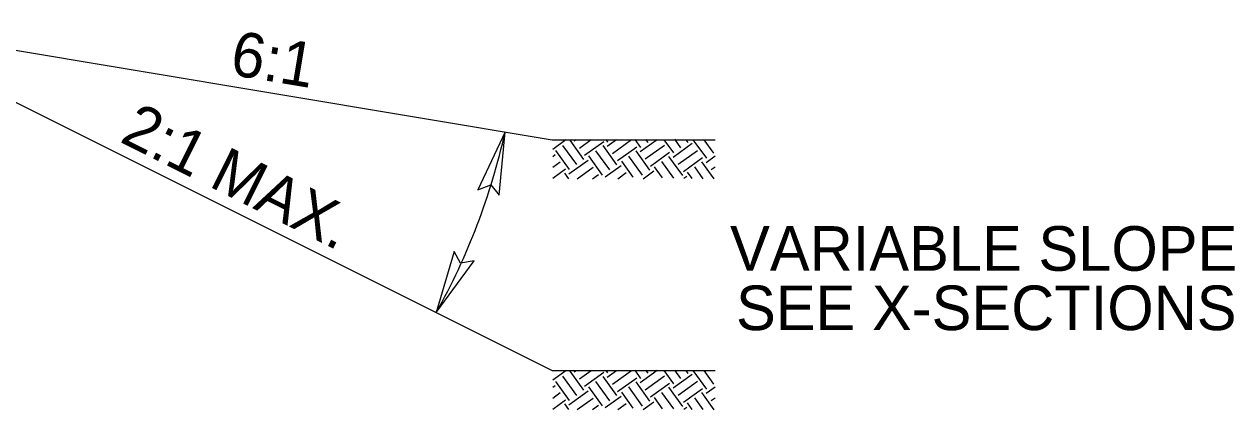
# Model space of a CAD drawing. Extents: x 1184121 to 1184397, y 1246506 to 1246661.
# Drawn here: x 1184249.47 to 1184276.61, y 1246565.28 to 1246573.92 of the extents above; entities that cross this region are included whole.
import ezdxf

# ---------------------------------------------------------------- set-up
doc = ezdxf.new("R2010")
doc.units = 0
doc.layers.add('Sheet Data Field CELL', color=7, linetype='Continuous')

msp = doc.modelspace()

# ---------------------------------------------------------------- linework, layer by layer
at = {"layer": 'Sheet Data Field CELL'}
for p, q in [((1184245.787, 1246573.92), (1184261.306, 1246571.333)), ((1184245.787, 1246573.92), (1184261.306, 1246566.16)), ((1184261.306, 1246571.333), (1184264.96, 1246571.333)), ((1184261.306, 1246571.333), (1184264.96, 1246571.333)), ((1184261.32, 1246571.122), (1184261.616, 1246571.334)), ((1184261.32, 1246571.122), (1184261.616, 1246571.334)), ((1184261.86, 1246570.776), (1184261.551, 1246571.206)), ((1184261.86, 1246570.776), (1184261.551, 1246571.206)), ((1184262.021, 1246570.892), (1184261.712, 1246571.322)), ((1184262.021, 1246570.892), (1184261.712, 1246571.322)), ((1184261.804, 1246571.307), (1184261.843, 1246571.335)), ((1184261.804, 1246571.307), (1184261.843, 1246571.335)), ((1184261.92, 1246571.146), (1184262.184, 1246571.336)), ((1184261.92, 1246571.146), (1184262.184, 1246571.336)), ((1184262.036, 1246570.985), (1184262.466, 1246571.293)), ((1184262.036, 1246570.985), (1184262.466, 1246571.293)), ((1184262.759, 1246570.771), (1184262.45, 1246571.201)), ((1184262.759, 1246570.771), (1184262.45, 1246571.201)), ((1184262.558, 1246571.278), (1184262.516, 1246571.337)), ((1184262.558, 1246571.278), (1184262.516, 1246571.337)), ((1184262.543, 1246571.186), (1184262.753, 1246571.337)), ((1184262.543, 1246571.186), (1184262.753, 1246571.337)), ((1184262.659, 1246571.025), (1184263.088, 1246571.334)), ((1184262.659, 1246571.025), (1184263.088, 1246571.334)), ((1184262.774, 1246570.864), (1184263.204, 1246571.172)), ((1184262.774, 1246570.864), (1184263.204, 1246571.172)), ((1184263.296, 1246571.157), (1184263.166, 1246571.338)), ((1184263.296, 1246571.157), (1184263.166, 1246571.338)), ((1184263.281, 1246571.065), (1184263.664, 1246571.34)), ((1184263.281, 1246571.065), (1184263.664, 1246571.34)), ((1184263.397, 1246570.904), (1184263.827, 1246571.213)), ((1184263.397, 1246570.904), (1184263.827, 1246571.213)), ((1184263.457, 1246571.273), (1184263.41, 1246571.339)), ((1184263.457, 1246571.273), (1184263.41, 1246571.339)), ((1184264.035, 1246571.036), (1184263.821, 1246571.333)), ((1184264.035, 1246571.036), (1184263.821, 1246571.333)), ((1184264.02, 1246570.944), (1184264.449, 1246571.253)), ((1184264.02, 1246570.944), (1184264.449, 1246571.253)), ((1184264.196, 1246571.152), (1184264.06, 1246571.341)), ((1184264.196, 1246571.152), (1184264.06, 1246571.341)), ((1184264.357, 1246571.268), (1184264.31, 1246571.333)), ((1184264.357, 1246571.268), (1184264.31, 1246571.333)), ((1184264.773, 1246570.915), (1184264.473, 1246571.333)), ((1184264.773, 1246570.915), (1184264.473, 1246571.333)), ((1184264.934, 1246571.031), (1184264.717, 1246571.333)), ((1184264.934, 1246571.031), (1184264.717, 1246571.333)), ((1184261.32, 1246570.959), (1184261.375, 1246570.998)), ((1184261.32, 1246570.959), (1184261.375, 1246570.998)), ((1184261.699, 1246570.661), (1184261.39, 1246571.09)), ((1184261.699, 1246570.661), (1184261.39, 1246571.09)), ((1184261.683, 1246570.568), (1184262.113, 1246570.877)), ((1184261.683, 1246570.568), (1184262.113, 1246570.877)), ((1184262.437, 1246570.54), (1184262.128, 1246570.969)), ((1184262.437, 1246570.54), (1184262.128, 1246570.969)), ((1184262.598, 1246570.656), (1184262.289, 1246571.085)), ((1184262.598, 1246570.656), (1184262.289, 1246571.085)), ((1184263.124, 1246570.49), (1184262.867, 1246570.849)), ((1184263.124, 1246570.49), (1184262.867, 1246570.849)), ((1184263.337, 1246570.535), (1184263.028, 1246570.964)), ((1184263.337, 1246570.535), (1184263.028, 1246570.964)), ((1184263.498, 1246570.65), (1184263.189, 1246571.08)), ((1184263.498, 1246570.65), (1184263.189, 1246571.08)), ((1184263.513, 1246570.743), (1184263.942, 1246571.051)), ((1184263.513, 1246570.743), (1184263.942, 1246571.051)), ((1184264.033, 1246570.472), (1184263.766, 1246570.843)), ((1184264.033, 1246570.472), (1184263.766, 1246570.843)), ((1184264.236, 1246570.53), (1184263.927, 1246570.959)), ((1184264.236, 1246570.53), (1184263.927, 1246570.959)), ((1184264.135, 1246570.783), (1184264.565, 1246571.092)), ((1184264.135, 1246570.783), (1184264.565, 1246571.092)), ((1184264.251, 1246570.622), (1184264.681, 1246570.931)), ((1184264.251, 1246570.622), (1184264.681, 1246570.931)), ((1184264.758, 1246570.823), (1184264.96, 1246570.968)), ((1184264.758, 1246570.823), (1184264.96, 1246570.968)), ((1184261.32, 1246570.714), (1184261.49, 1246570.837)), ((1184261.32, 1246570.714), (1184261.49, 1246570.837)), ((1184261.32, 1246570.47), (1184261.606, 1246570.676)), ((1184261.32, 1246570.47), (1184261.606, 1246570.676)), ((1184261.681, 1246570.459), (1184261.591, 1246570.583)), ((1184261.681, 1246570.459), (1184261.591, 1246570.583)), ((1184261.871, 1246570.459), (1184262.229, 1246570.716)), ((1184261.871, 1246570.459), (1184262.229, 1246570.716)), ((1184262.499, 1246570.503), (1184262.852, 1246570.756)), ((1184262.499, 1246570.503), (1184262.852, 1246570.756)), ((1184262.778, 1246570.459), (1184262.967, 1246570.595)), ((1184262.778, 1246570.459), (1184262.967, 1246570.595)), ((1184263.345, 1246570.459), (1184263.59, 1246570.635)), ((1184263.345, 1246570.459), (1184263.59, 1246570.635)), ((1184263.785, 1246570.477), (1184263.605, 1246570.728)), ((1184263.785, 1246570.477), (1184263.605, 1246570.728)), ((1184264.446, 1246570.464), (1184264.343, 1246570.607)), ((1184264.446, 1246570.464), (1184264.343, 1246570.607)), ((1184264.694, 1246570.459), (1184264.505, 1246570.723)), ((1184264.694, 1246570.459), (1184264.505, 1246570.723)), ((1184264.942, 1246570.454), (1184264.666, 1246570.838)), ((1184264.942, 1246570.454), (1184264.666, 1246570.838)), ((1184264.874, 1246570.662), (1184264.96, 1246570.724)), ((1184264.874, 1246570.662), (1184264.96, 1246570.724)), ((1184262.211, 1246570.459), (1184262.345, 1246570.555)), ((1184262.211, 1246570.459), (1184262.345, 1246570.555)), ((1184264.263, 1246570.467), (1184264.328, 1246570.514)), ((1184264.263, 1246570.467), (1184264.328, 1246570.514)), ((1184261.306, 1246566.16), (1184264.96, 1246566.16)), ((1184261.306, 1246566.16), (1184264.96, 1246566.16)), ((1184261.32, 1246565.948), (1184261.616, 1246566.161)), ((1184261.32, 1246565.948), (1184261.616, 1246566.161)), ((1184261.86, 1246565.603), (1184261.551, 1246566.033)), ((1184261.86, 1246565.603), (1184261.551, 1246566.033)), ((1184262.021, 1246565.719), (1184261.712, 1246566.149)), ((1184262.021, 1246565.719), (1184261.712, 1246566.149)), ((1184261.804, 1246566.134), (1184261.843, 1246566.162)), ((1184261.804, 1246566.134), (1184261.843, 1246566.162)), ((1184261.92, 1246565.973), (1184262.184, 1246566.163)), ((1184261.92, 1246565.973), (1184262.184, 1246566.163)), ((1184262.036, 1246565.811), (1184262.466, 1246566.12)), ((1184262.036, 1246565.811), (1184262.466, 1246566.12)), ((1184262.759, 1246565.598), (1184262.45, 1246566.028)), ((1184262.759, 1246565.598), (1184262.45, 1246566.028)), ((1184262.558, 1246566.105), (1184262.516, 1246566.163)), ((1184262.558, 1246566.105), (1184262.516, 1246566.163)), ((1184262.543, 1246566.013), (1184262.753, 1246566.164)), ((1184262.543, 1246566.013), (1184262.753, 1246566.164)), ((1184262.659, 1246565.852), (1184263.088, 1246566.16)), ((1184262.659, 1246565.852), (1184263.088, 1246566.16)), ((1184262.774, 1246565.691), (1184263.204, 1246565.999)), ((1184262.774, 1246565.691), (1184263.204, 1246565.999)), ((1184263.296, 1246565.984), (1184263.166, 1246566.165)), ((1184263.296, 1246565.984), (1184263.166, 1246566.165)), ((1184263.281, 1246565.892), (1184263.664, 1246566.167)), ((1184263.281, 1246565.892), (1184263.664, 1246566.167)), ((1184263.397, 1246565.731), (1184263.827, 1246566.04)), ((1184263.397, 1246565.731), (1184263.827, 1246566.04)), ((1184263.457, 1246566.1), (1184263.41, 1246566.166)), ((1184263.457, 1246566.1), (1184263.41, 1246566.166)), ((1184264.035, 1246565.863), (1184263.821, 1246566.16)), ((1184264.035, 1246565.863), (1184263.821, 1246566.16)), ((1184264.02, 1246565.771), (1184264.449, 1246566.08)), ((1184264.02, 1246565.771), (1184264.449, 1246566.08)), ((1184264.196, 1246565.979), (1184264.06, 1246566.168)), ((1184264.196, 1246565.979), (1184264.06, 1246566.168)), ((1184264.357, 1246566.095), (1184264.31, 1246566.16)), ((1184264.357, 1246566.095), (1184264.31, 1246566.16)), ((1184264.773, 1246565.742), (1184264.473, 1246566.16)), ((1184264.773, 1246565.742), (1184264.473, 1246566.16)), ((1184264.934, 1246565.858), (1184264.717, 1246566.16)), ((1184264.934, 1246565.858), (1184264.717, 1246566.16)), ((1184261.32, 1246565.786), (1184261.375, 1246565.825)), ((1184261.32, 1246565.786), (1184261.375, 1246565.825)), ((1184261.699, 1246565.488), (1184261.39, 1246565.917)), ((1184261.699, 1246565.488), (1184261.39, 1246565.917)), ((1184261.683, 1246565.395), (1184262.113, 1246565.704)), ((1184261.683, 1246565.395), (1184262.113, 1246565.704)), ((1184262.437, 1246565.367), (1184262.128, 1246565.796)), ((1184262.437, 1246565.367), (1184262.128, 1246565.796)), ((1184262.598, 1246565.482), (1184262.289, 1246565.912)), ((1184262.598, 1246565.482), (1184262.289, 1246565.912)), ((1184263.337, 1246565.362), (1184263.028, 1246565.791)), ((1184263.337, 1246565.362), (1184263.028, 1246565.791)), ((1184263.498, 1246565.477), (1184263.189, 1246565.907)), ((1184263.498, 1246565.477), (1184263.189, 1246565.907)), ((1184263.513, 1246565.57), (1184263.942, 1246565.878)), ((1184263.513, 1246565.57), (1184263.942, 1246565.878)), ((1184264.236, 1246565.356), (1184263.927, 1246565.786)), ((1184264.236, 1246565.356), (1184263.927, 1246565.786)), ((1184264.135, 1246565.61), (1184264.565, 1246565.919)), ((1184264.135, 1246565.61), (1184264.565, 1246565.919)), ((1184264.251, 1246565.449), (1184264.681, 1246565.758)), ((1184264.251, 1246565.449), (1184264.681, 1246565.758)), ((1184264.758, 1246565.65), (1184264.96, 1246565.795)), ((1184264.758, 1246565.65), (1184264.96, 1246565.795)), ((1184261.32, 1246565.541), (1184261.49, 1246565.664)), ((1184261.32, 1246565.541), (1184261.49, 1246565.664)), ((1184261.32, 1246565.297), (1184261.606, 1246565.503)), ((1184261.32, 1246565.297), (1184261.606, 1246565.503)), ((1184261.871, 1246565.286), (1184262.229, 1246565.543)), ((1184261.871, 1246565.286), (1184262.229, 1246565.543)), ((1184262.499, 1246565.33), (1184262.852, 1246565.583)), ((1184262.499, 1246565.33), (1184262.852, 1246565.583)), ((1184262.778, 1246565.286), (1184262.967, 1246565.422)), ((1184262.778, 1246565.286), (1184262.967, 1246565.422)), ((1184263.124, 1246565.317), (1184262.867, 1246565.675)), ((1184263.124, 1246565.317), (1184262.867, 1246565.675)), ((1184263.345, 1246565.286), (1184263.59, 1246565.462)), ((1184263.345, 1246565.286), (1184263.59, 1246565.462)), ((1184263.785, 1246565.304), (1184263.605, 1246565.555)), ((1184263.785, 1246565.304), (1184263.605, 1246565.555)), ((1184264.033, 1246565.299), (1184263.766, 1246565.67)), ((1184264.033, 1246565.299), (1184263.766, 1246565.67)), ((1184264.446, 1246565.29), (1184264.343, 1246565.434)), ((1184264.446, 1246565.29), (1184264.343, 1246565.434)), ((1184264.694, 1246565.285), (1184264.505, 1246565.549)), ((1184264.694, 1246565.285), (1184264.505, 1246565.549)), ((1184264.942, 1246565.281), (1184264.666, 1246565.665)), ((1184264.942, 1246565.281), (1184264.666, 1246565.665)), ((1184264.874, 1246565.489), (1184264.96, 1246565.551)), ((1184264.874, 1246565.489), (1184264.96, 1246565.551)), ((1184261.681, 1246565.286), (1184261.591, 1246565.41)), ((1184261.681, 1246565.286), (1184261.591, 1246565.41)), ((1184262.211, 1246565.286), (1184262.345, 1246565.382)), ((1184262.211, 1246565.286), (1184262.345, 1246565.382)), ((1184264.263, 1246565.294), (1184264.328, 1246565.341)), ((1184264.263, 1246565.294), (1184264.328, 1246565.341))]:
    msp.add_line(p, q, dxfattribs=at)
for points in [[(1184260.118, 1246570.088), (1184260.254, 1246571.509), (1184259.642, 1246570.21), (1184259.93, 1246570.318)], [(1184259.114, 1246568.826), (1184258.711, 1246567.458), (1184259.559, 1246568.616), (1184259.256, 1246568.565)]]:
    msp.add_lwpolyline(points, close=True, dxfattribs=at)
msp.add_arc((1184245.612, 1246574.766), 15, 330.8419, 347.4573, dxfattribs=at)

# ---------------------------------------------------------------- texts
for s, rotation, p in [('6:1', 350.5375, (1184254.059, 1246572.795)), ('2:1 MAX.', 333.4348, (1184251.589, 1246571.298)), ('VARIABLE SLOPE', 360, (1184265.297, 1246568.395)), ('SEE X-SECTIONS', 360, (1184265.43, 1246567.065))]:
    msp.add_text(s, height=1, rotation=rotation, dxfattribs=at).set_placement(p)

doc.saveas('drawing.dxf')
